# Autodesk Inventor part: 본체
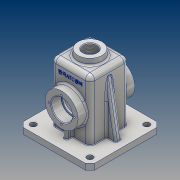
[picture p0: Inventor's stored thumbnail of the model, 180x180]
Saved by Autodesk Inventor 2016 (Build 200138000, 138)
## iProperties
Created: 2018-10
Part Number: 본체
Material: 알루미늄 6061
Document SubType Name: Modeling
Designer: user
Density: 2.7 g/cm^3
Appearance: 알루미늄 - 평지
Mass: 794.227 g
Surface Area: 899.501 cm^2
Volume: 294.158 cm^3
Author: user
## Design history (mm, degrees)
sketch "스케치1"
  geometry: L1 (-60, 60)-(60, 60); L2 (60, 60)-(60, -60); L3 (60, -60)-(-60, -60); L4 (-60, -60)-(-60, 60); L5 (-60, 60)-(60, -60); L6 (60, 60)-(-60, -60); 1 further point
  constraints: 12 end point, 2 midpoint, 2 parallel, 1 horizontal, 1 perpendicular
  dimensions: "d0" = 120 distance of L1.start L1.end; "d1" = 120 distance of L1.end L2.end
extrude "돌출1" new body sketch "스케치1" distance "d2" = 10; taper "d3" = 0 deg
sketch "스케치2"
  geometry: L1 (32.5, -32.5)-(-32.5, -32.5); L2 (-32.5, -32.5)-(-32.5, 32.5); L3 (-32.5, 32.5)-(32.5, 32.5); L4 (32.5, 32.5)-(32.5, -32.5); L5 (32.5, -32.5)-(-32.5, 32.5); L6 (-32.5, -32.5)-(32.5, 32.5); 1 further point
  constraints: 12 end point, 2 midpoint, 2 parallel, 1 horizontal, 1 perpendicular
  dimensions: "d4" = 65 distance of L1.start L1.end; "d5" = 65 distance of L1.end L2.end
extrude "돌출2" join sketch "스케치2" distance "d6" = 110; taper "d7" = 0 deg
fillet "모깎기1" dims "d8" = 8
feature "쉘1" dims "d9" = 10, "d10" = 5
sketch "스케치4"
  geometry: L1 (-35.5, 102)-(84.5, 102) reference; C1 r 27.5 at (24.5, 47); 2 further points
  constraints: 1 centre point, 1 midpoint, 1 vertical alignment
  dimensions: "d14" = 55 diameter of C1; "d15" = 55 distance from line of L1 C1.centre
extrude "돌출4" join sketch "스케치4" distance "d16" = 15; taper "d17" = 0 deg
sketch "스케치5"
  geometry: C1 r 27.5 at (0, 0) reference; 1 further point
hole "구멍1" sketch "스케치5" at (0, 0) diameter "d18" = 30; stored, may be unused: countersink angle "d22" = 90 deg, drill point angle "d24" = 118 deg; dims "d19" = 6, "d20" = 35, "d21" = 17, "d23" = 8
sketch "스케치6"
  geometry: C1 r 17.5 at (0, 0) reference; C2 r 27.5 at (0, 0) reference; 2 further points
  constraints: 1 vertical alignment
  dimensions: "d25" = 21 distance of C1.centre point (0, -21)
hole "구멍2" sketch "스케치6" at (0, -21) diameter "d26" = 3.242; stored, may be unused: countersink angle "d30" = 90 deg, drill point angle "d32" = 118 deg; dims "d27" = 8, "d28" = 35, "d29" = 17, "d31" = 10
sketch "스케치7"
  geometry: L1 (60, 10)-(60, 0) reference; L2 (60, 0)-(27.5, 0) reference; L3 (27.5, 0)-(27.5, 102) reference; L4 (24.5, 105)-(-24.5, 105) reference; L5 (-27.5, 102)-(-27.5, 0) reference; L6 (-27.5, 0)-(-60, 0) reference; L7 (-60, 0)-(-60, 10) reference; L8 (-60, 10)-(-32.5, 10) reference; L9 (-32.5, 10)-(-32.5, 102) reference; L10 (-24.5, 110)-(24.5, 110) reference; L11 (32.5, 102)-(32.5, 10) reference; L12 (32.5, 10)-(60, 10) reference; L13 (48, 10)-(32.5, 97.905); L14 (32.5, 102)-(32.5, 10) reference; L15 (60, 10)-(-60, 10) reference; L16 (-48, 10)-(-32.5, 97.905); A1 r 3 centre (24.5, 102) between (27.5, 102) and (24.5, 105) reference; A2 r 3 centre (-24.5, 102) between (-24.5, 105) and (-27.5, 102) reference; A3 r 8 centre (-24.5, 102) between (-24.5, 110) and (-32.5, 102) reference; A4 r 8 centre (24.5, 102) between (32.5, 102) and (24.5, 110) reference; 1 further point
  constraints: 4 end point, 4 point on line
  dimensions: "d36" = 12 distance of L1.start L13.start; "d37" = 10 deg angle of L1 L13; "d38" = 12 distance of L16.start L7.end; "d39" = 10 deg angle of L16 L7
  node "절단 모서리 투영1"
feature "리브1" dims "d40" = 1, "d41" = 10, "d42" = 0, "d43" = 0, "d44" = 1, "d45" = 1
feature "리브2" dims "d46" = 1, "d47" = 10, "d48" = 0, "d49" = 0, "d50" = 1, "d51" = 1
sketch "스케치8"
  geometry: L1 (-32.5, 27.5)-(-47.5, 27.5) reference; L2 (-47.5, 27.5)-(-47.5, 32.379) reference; L3 (-47.5, 32.379)-(-37.5, 32.379) reference; L4 (-37.5, 32.379)-(-36.526, 34) reference; L5 (-36.526, 34)-(-37.5, 35.621) reference; L6 (-37.5, 35.621)-(-47.5, 35.621) reference; L7 (-47.5, 35.621)-(-47.5, 37.5) reference; L8 (-47.5, 37.5)-(-30.5, 37.5) reference; L9 (-30.5, 37.5)-(-30.5, 40) reference; L10 (-30.5, 40)-(-27.5, 40) reference; L11 (-27.5, 40)-(-27.5, 0) reference; L12 (-27.5, 0)-(-60, 0) reference; L13 (-60, 0)-(-60, 10) reference; L14 (-60, 10)-(-32.5, 10) reference; L15 (-32.5, 10)-(-32.5, 27.5) reference; L16 (47.5, 27.5)-(32.5, 27.5) reference; L17 (32.5, 27.5)-(32.5, 10) reference; L18 (32.5, 10)-(60, 10) reference; L19 (60, 10)-(60, 0) reference; L20 (60, 0)-(27.5, 0) reference; L21 (27.5, 0)-(27.5, 40) reference; L22 (27.5, 40)-(30.5, 40) reference; L23 (30.5, 40)-(30.5, 37.5) reference; L24 (30.5, 37.5)-(47.5, 37.5) reference; L25 (47.5, 37.5)-(47.5, 35.621) reference; L26 (47.5, 35.621)-(37.5, 35.621) reference; L27 (37.5, 35.621)-(36.526, 34) reference; L28 (36.526, 34)-(37.5, 32.379) reference; L29 (37.5, 32.379)-(47.5, 32.379) reference; L30 (47.5, 32.379)-(47.5, 27.5) reference; L31 (-27.5, 102)-(-27.5, 70) reference; L32 (-27.5, 70)-(-30.5, 70) reference; L33 (-30.5, 70)-(-30.5, 72.5) reference; L34 (-30.5, 72.5)-(-47.5, 72.5) reference; L35 (-47.5, 72.5)-(-47.5, 74.379) reference; L36 (-47.5, 74.379)-(-37.5, 74.379) reference; L37 (-37.5, 74.379)-(-36.526, 76) reference; L38 (-36.526, 76)-(-37.5, 77.621) reference; L39 (-37.5, 77.621)-(-47.5, 77.621) reference; L40 (-47.5, 77.621)-(-47.5, 82.5) reference; L41 (-47.5, 82.5)-(-32.5, 82.5) reference; L42 (-32.5, 82.5)-(-32.5, 102) reference; L43 (-24.5, 110)-(24.5, 110) reference; L44 (32.5, 102)-(32.5, 82.5) reference; L45 (32.5, 82.5)-(47.5, 82.5) reference; L46 (47.5, 82.5)-(47.5, 77.621) reference; L47 (47.5, 77.621)-(37.5, 77.621) reference; L48 (37.5, 77.621)-(36.526, 76) reference; L49 (36.526, 76)-(37.5, 74.379) reference; L50 (37.5, 74.379)-(47.5, 74.379) reference; L51 (47.5, 74.379)-(47.5, 72.5) reference; L52 (47.5, 72.5)-(30.5, 72.5) reference; L53 (30.5, 72.5)-(30.5, 70) reference; L54 (30.5, 70)-(27.5, 70) reference; L55 (27.5, 70)-(27.5, 102) reference; L56 (24.5, 105)-(-24.5, 105) reference; L57 (-42.5, 27.5)-(-42.5, 10); L58 (60, 10)-(-60, 10) reference; L59 (42.5, 27.5)-(42.5, 10); A1 r 3 centre (-24.5, 102) between (-24.5, 105) and (-27.5, 102) reference; A2 r 8 centre (-24.5, 102) between (-24.5, 110) and (-32.5, 102) reference; A3 r 8 centre (24.5, 102) between (32.5, 102) and (24.5, 110) reference; A4 r 3 centre (24.5, 102) between (27.5, 102) and (24.5, 105) reference; 1 further point
  constraints: 4 end point, 4 point on line, 2 perpendicular
  dimensions: "d52" = 15 distance between parallel lines of L11 L57; "d53" = 15 distance between parallel lines of L21 L59
  node "절단 모서리 투영2"
feature "리브3" dims "d54" = 1, "d55" = 6, "d56" = 0, "d57" = 0, "d58" = 1, "d59" = 1
feature "리브4" dims "d60" = 1, "d61" = 6, "d62" = 0, "d63" = 0, "d64" = 1, "d65" = 1
node "작업 평면1"
sketch "스케치9"
  geometry: C1 r 20 at (0, 0); 1 further point
  constraints: 1 centre point, 1 coincident
  dimensions: "d67" = 40 diameter of C1
extrude "돌출5" join sketch "스케치9" stored distance "d68" = 15; taper "d69" = 7 deg
hole "구멍3" diameter "d72" = 22.835; stored, may be unused: countersink angle "d76" = 90 deg, drill point angle "d78" = 118 deg; dims "d70" = 10, "d71" = 10, "d73" = 50, "d74" = 4, "d75" = 2, "d77" = 59.3
sketch "스케치11"
  geometry: C1 r 5 at (47.5, -47.5); C2 r 5 at (-47.5, -47.5); C3 r 5 at (47.5, 47.5); C4 r 5 at (-47.5, 47.5); 1 further point
  constraints: 4 centre point, 1 vertical alignment
  dimensions: "d79" = 10 diameter of C1; "d80" = 10 diameter of C2; "d81" = 10 diameter of C3; "d82" = 10 diameter of C4; "d83" = 95 distance of C2.centre C1.centre; "d84" = 95 distance of C4.centre C2.centre; "d88" = 47.5 horizontal distance of point (0, 0) C3.centre; "d89" = 47.5 horizontal distance of point (0, 0) C3.centre; "d90" = 47.5 horizontal distance of C1.centre point (0, 0); "d91" = 47.5 horizontal distance of point (0, 0) C4.centre; "d92" = 47.5 horizontal distance of point (0, 0) C4.centre
extrude "돌출6" cut sketch "스케치11" stored distance "d102" = 10; taper "d103" = 0 deg
chamfer "모따기1" distance "d85" = 8; stored, may be unused: second distance "d86" = 2, angle "d87" = 45 deg
fillet "모깎기2" dims "d93" = 3
fillet "모깎기3" dims "d94" = 3
fillet "모깎기4" dims "d95" = 3
fillet "모깎기5" dims "d96" = 3
fillet "모깎기6" dims "d97" = 1
fillet "모깎기7" dims "d98" = 0.3
chamfer "모따기2" distance "d99" = 1; stored, may be unused: second distance "d100" = 2, angle "d101" = 45 deg
sketch "스케치14"
  geometry: L1 (4.5, 18)-(44.5, 18) reference; 3 further points
  constraints: 1 midpoint, 1 vertical alignment, 1 other
  dimensions: "d104" = 26 distance from line of L1 point (24.5, -8)
feature "엠보싱1" sketch "스케치14" dims "d105" = 0.5, "d106" = 0
fillet "모깎기8" dims "d107" = 3
node "솔리드1"
pattern_circular "원형 패턴1" dims angle "d34" = 360 deg
mirror "대칭1"
node "투영된 루프1"
node "투영된 루프2"
